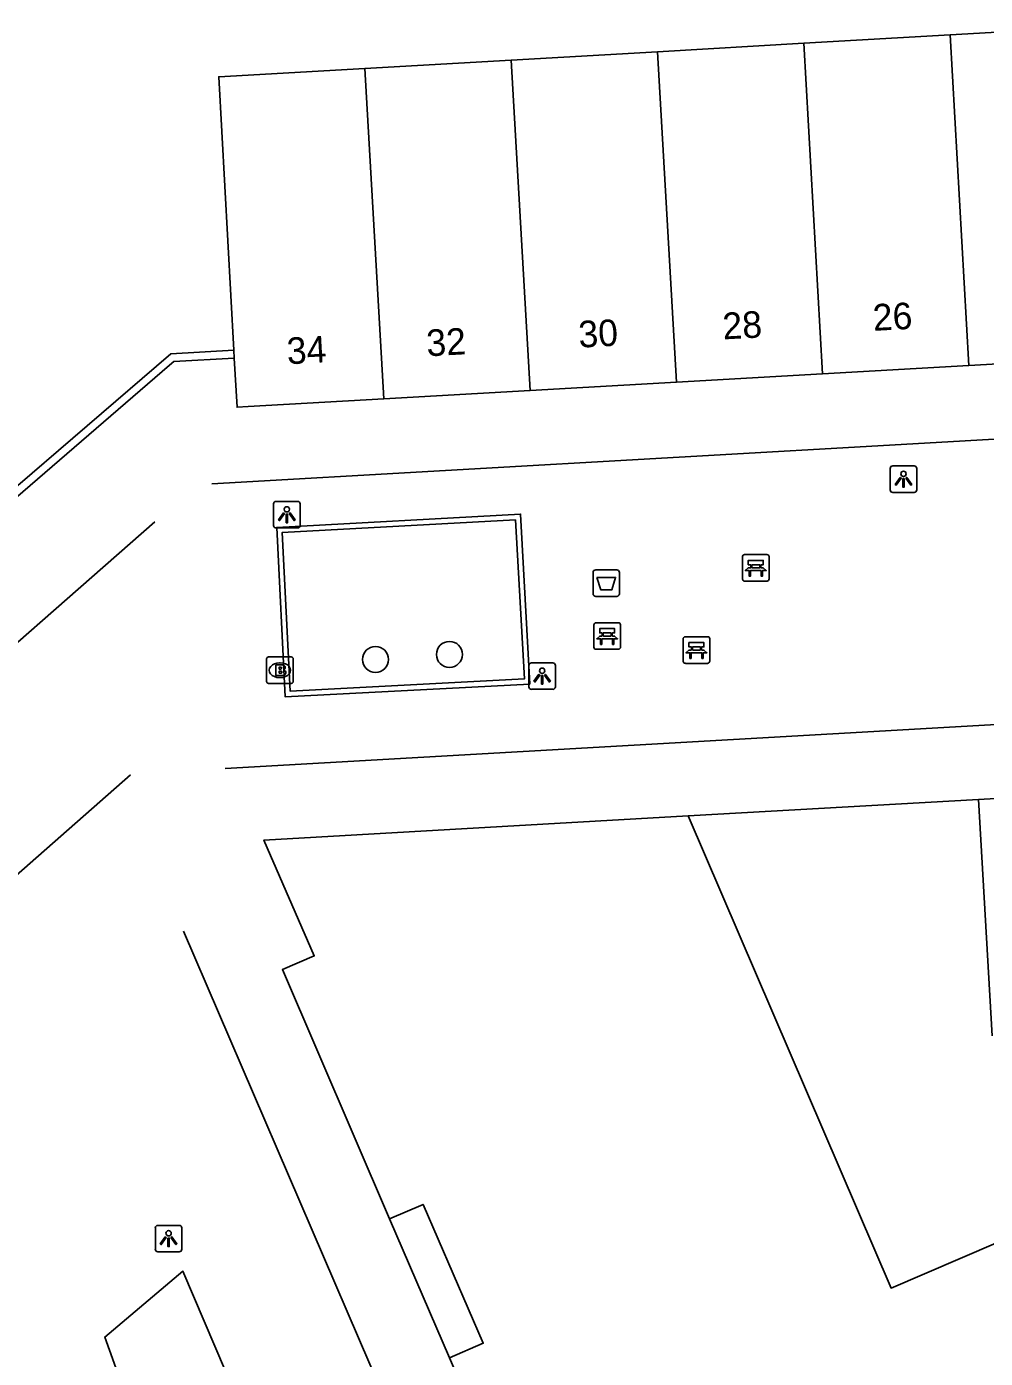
# Model space of a CAD drawing. Extents: x 155640 to 156810, y 382822 to 384046.
# Drawn here: x 156513.2 to 156549.2, y 383789.4 to 383839.5 of the extents above; entities that cross this region are included whole.
import ezdxf

# ---------------------------------------------------------------- set-up
doc = ezdxf.new("R2010")
doc.units = 0
for name, color, linetype in [('IMGEO_Afvalbak', 7, 'Continuous'), ('IMGEO_Bank', 7, 'Continuous'), ('IMGEO_Boom', 7, 'Continuous'), ('IMGEO_Brandkraan', 7, 'Continuous'), ('IMGEO_Lichtpunt', 7, 'Continuous'), ('IMGEO_Lijnafwatering', 7, 'Continuous'), ('IMGEO_Muur', 7, 'Continuous'), ('IMGEO_Pand', 7, 'Continuous'), ('IMGEO_Pand_nummerreeks', 7, 'Continuous'), ('IMGEO_Pand_overbouw', 7, 'Continuous'), ('IMGEO_Voetgangersgebied_open', 7, 'Continuous'), ('IMGEO_Voetpad_open', 7, 'Continuous')]:
    doc.layers.add(name, color=color, linetype=linetype)

msp = doc.modelspace()

# ---------------------------------------------------------------- linework, layer by layer
at = {"layer": 'IMGEO_Afvalbak'}
for p, q in [((156534.493, 383818.161), (156534.493, 383818.961)), ((156534.493, 383818.961), (156534.493, 383818.161)), ((156534.593, 383819.061), (156535.383, 383819.061)), ((156535.383, 383819.061), (156534.593, 383819.061)), ((156535.483, 383818.961), (156535.483, 383818.161)), ((156535.483, 383818.161), (156535.483, 383818.961)), ((156535.383, 383818.061), (156534.593, 383818.061)), ((156534.593, 383818.061), (156535.383, 383818.061))]:
    msp.add_line(p, q, dxfattribs=at)
msp.add_lwpolyline([(156534.636, 383818.775), (156535.34, 383818.775), (156535.191, 383818.305), (156534.785, 383818.305), (156534.636, 383818.775)], dxfattribs=at)
for centre, start, end in [((156534.593, 383818.961), 90, 180), ((156534.593, 383818.961), 90, 180), ((156535.383, 383818.961), 0, 90), ((156535.383, 383818.961), 360, 90), ((156534.593, 383818.161), 180, 270), ((156534.593, 383818.161), 180, 270), ((156535.383, 383818.161), 270, 0), ((156535.383, 383818.161), 270, 0)]:
    msp.add_arc(centre, 0.1, start, end, dxfattribs=at)
at = {"layer": 'IMGEO_Bank'}
for p, q in [((156540.11, 383818.709), (156540.11, 383819.55)), ((156540.11, 383819.55), (156540.11, 383818.709)), ((156540.185, 383819.634), (156541.026, 383819.634)), ((156541.026, 383819.634), (156540.185, 383819.634)), ((156541.11, 383819.559), (156541.11, 383818.718)), ((156541.11, 383818.718), (156541.11, 383819.559)), ((156540.807, 383819.032), (156540.414, 383819.032)), ((156540.419, 383819.14), (156540.419, 383819.246)), ((156540.463, 383819.246), (156540.463, 383819.14)), ((156540.751, 383819.252), (156540.469, 383819.252)), ((156540.469, 383819.134), (156540.751, 383819.134)), ((156540.757, 383819.14), (156540.757, 383819.246)), ((156540.801, 383819.246), (156540.801, 383819.14)), ((156541.035, 383818.634), (156540.194, 383818.634)), ((156540.194, 383818.634), (156541.035, 383818.634)), ((156534.523, 383816.146), (156534.523, 383816.987)), ((156534.523, 383816.987), (156534.523, 383816.146)), ((156534.598, 383817.071), (156535.439, 383817.071)), ((156535.439, 383817.071), (156534.598, 383817.071)), ((156535.523, 383816.996), (156535.523, 383816.155)), ((156535.523, 383816.155), (156535.523, 383816.996)), ((156535.22, 383816.469), (156534.827, 383816.469)), ((156534.832, 383816.577), (156534.832, 383816.683)), ((156534.876, 383816.683), (156534.876, 383816.577)), ((156535.164, 383816.689), (156534.882, 383816.689)), ((156534.882, 383816.571), (156535.164, 383816.571)), ((156535.17, 383816.577), (156535.17, 383816.683)), ((156535.214, 383816.683), (156535.214, 383816.577)), ((156537.88, 383815.618), (156537.88, 383816.459)), ((156537.88, 383816.459), (156537.88, 383815.618)), ((156537.955, 383816.543), (156538.796, 383816.543)), ((156538.796, 383816.543), (156537.955, 383816.543)), ((156538.88, 383816.468), (156538.88, 383815.627)), ((156538.88, 383815.627), (156538.88, 383816.468)), ((156535.448, 383816.071), (156534.607, 383816.071)), ((156534.607, 383816.071), (156535.448, 383816.071)), ((156538.577, 383815.941), (156538.184, 383815.941)), ((156538.189, 383816.049), (156538.189, 383816.155)), ((156538.233, 383816.155), (156538.233, 383816.049)), ((156538.521, 383816.161), (156538.239, 383816.161)), ((156538.239, 383816.043), (156538.521, 383816.043)), ((156538.527, 383816.049), (156538.527, 383816.155)), ((156538.571, 383816.155), (156538.571, 383816.049)), ((156538.805, 383815.543), (156537.964, 383815.543)), ((156537.964, 383815.543), (156538.805, 383815.543))]:
    msp.add_line(p, q, dxfattribs=at)
for points in [[(156540.413, 383819.252), (156540.327, 383819.252), (156540.327, 383819.413), (156540.89, 383819.413), (156540.89, 383819.252), (156540.807, 383819.252)], [(156540.357, 383819.032), (156540.215, 383819.032), (156540.327, 383819.134), (156540.413, 383819.134)], [(156540.407, 383819.025), (156540.407, 383818.818), (156540.364, 383818.818), (156540.364, 383819.025)], [(156540.807, 383819.134), (156540.89, 383819.134), (156541.002, 383819.032), (156540.863, 383819.032)], [(156540.857, 383819.025), (156540.857, 383818.818), (156540.813, 383818.818), (156540.813, 383819.025)], [(156534.826, 383816.689), (156534.74, 383816.689), (156534.74, 383816.85), (156535.303, 383816.85), (156535.303, 383816.689), (156535.22, 383816.689)], [(156534.77, 383816.469), (156534.628, 383816.469), (156534.74, 383816.571), (156534.826, 383816.571)], [(156534.82, 383816.462), (156534.82, 383816.255), (156534.777, 383816.255), (156534.777, 383816.462)], [(156535.22, 383816.571), (156535.303, 383816.571), (156535.415, 383816.469), (156535.276, 383816.469)], [(156535.27, 383816.462), (156535.27, 383816.255), (156535.226, 383816.255), (156535.226, 383816.462)], [(156538.183, 383816.161), (156538.097, 383816.161), (156538.097, 383816.322), (156538.66, 383816.322), (156538.66, 383816.161), (156538.577, 383816.161)], [(156538.127, 383815.941), (156537.985, 383815.941), (156538.097, 383816.043), (156538.183, 383816.043)], [(156538.177, 383815.934), (156538.177, 383815.727), (156538.134, 383815.727), (156538.134, 383815.934)], [(156538.577, 383816.043), (156538.66, 383816.043), (156538.772, 383815.941), (156538.633, 383815.941)], [(156538.627, 383815.934), (156538.627, 383815.727), (156538.583, 383815.727), (156538.583, 383815.934)]]:
    msp.add_lwpolyline(points, dxfattribs=at)
for centre, radius, start, end in [((156540.188, 383819.556), 0.0779, 92.4484, 184.2845), ((156540.188, 383819.556), 0.0779, 92.4484, 184.2845), ((156541.032, 383819.556), 0.0779, 2.4484, 94.2845), ((156541.032, 383819.556), 0.0779, 2.4484, 94.2845), ((156540.357, 383819.025), 0.00671, 2.8957, 87.1043), ((156540.414, 383819.025), 0.00671, 92.8957, 177.1043), ((156540.412, 383819.245), 0.00671, 2.8957, 87.1043), ((156540.412, 383819.141), 0.00671, 272.8957, 357.1043), ((156540.469, 383819.245), 0.00671, 92.8957, 177.1043), ((156540.469, 383819.141), 0.00671, 182.8957, 267.1043), ((156540.751, 383819.245), 0.00671, 2.8957, 87.1043), ((156540.751, 383819.141), 0.00671, 272.8957, 357.1043), ((156540.808, 383819.245), 0.00671, 92.8957, 177.1043), ((156540.808, 383819.141), 0.00671, 182.8957, 267.1043), ((156540.806, 383819.025), 0.00671, 2.8957, 87.1043), ((156540.863, 383819.025), 0.00671, 92.8957, 177.1043), ((156540.188, 383818.712), 0.0779, 182.4484, 274.2845), ((156540.188, 383818.712), 0.0779, 182.4484, 274.2845), ((156541.032, 383818.712), 0.0779, 272.4484, 4.2845), ((156541.032, 383818.712), 0.0779, 272.4484, 4.2845), ((156534.601, 383816.993), 0.0779, 92.4484, 184.2845), ((156534.601, 383816.993), 0.0779, 92.4484, 184.2845), ((156535.445, 383816.993), 0.0779, 2.4484, 94.2845), ((156535.445, 383816.993), 0.0779, 2.4484, 94.2845), ((156534.77, 383816.462), 0.00671, 2.8957, 87.1043), ((156534.827, 383816.462), 0.00671, 92.8957, 177.1043), ((156534.825, 383816.682), 0.00671, 2.8957, 87.1043), ((156534.825, 383816.578), 0.00671, 272.8957, 357.1043), ((156534.882, 383816.682), 0.00671, 92.8957, 177.1043), ((156534.882, 383816.578), 0.00671, 182.8957, 267.1043), ((156535.164, 383816.682), 0.00671, 2.8957, 87.1043), ((156535.164, 383816.578), 0.00671, 272.8957, 357.1043), ((156535.221, 383816.682), 0.00671, 92.8957, 177.1043), ((156535.221, 383816.578), 0.00671, 182.8957, 267.1043), ((156535.219, 383816.462), 0.00671, 2.8957, 87.1043), ((156535.276, 383816.462), 0.00671, 92.8957, 177.1043), ((156537.958, 383816.465), 0.0779, 92.4484, 184.2845), ((156537.958, 383816.465), 0.0779, 92.4484, 184.2845), ((156538.802, 383816.465), 0.0779, 2.4484, 94.2845), ((156538.802, 383816.465), 0.0779, 2.4484, 94.2845), ((156534.601, 383816.149), 0.0779, 182.4484, 274.2845), ((156534.601, 383816.149), 0.0779, 182.4484, 274.2845), ((156535.445, 383816.149), 0.0779, 272.4484, 4.2845), ((156535.445, 383816.149), 0.0779, 272.4484, 4.2845), ((156538.127, 383815.934), 0.00671, 2.8957, 87.1043), ((156538.184, 383815.934), 0.00671, 92.8957, 177.1043), ((156538.182, 383816.154), 0.00671, 2.8957, 87.1043), ((156538.182, 383816.05), 0.00671, 272.8957, 357.1043), ((156538.239, 383816.154), 0.00671, 92.8957, 177.1043), ((156538.239, 383816.05), 0.00671, 182.8957, 267.1043), ((156538.521, 383816.154), 0.00671, 2.8957, 87.1043), ((156538.521, 383816.05), 0.00671, 272.8957, 357.1043), ((156538.578, 383816.154), 0.00671, 92.8957, 177.1043), ((156538.578, 383816.05), 0.00671, 182.8957, 267.1043), ((156538.576, 383815.934), 0.00671, 2.8957, 87.1043), ((156538.633, 383815.934), 0.00671, 92.8957, 177.1043), ((156537.958, 383815.621), 0.0779, 182.4484, 274.2845), ((156537.958, 383815.621), 0.0779, 182.4484, 274.2845), ((156538.802, 383815.621), 0.0779, 272.4484, 4.2845), ((156538.802, 383815.621), 0.0779, 272.4484, 4.2845)]:
    msp.add_arc(centre, radius, start, end, dxfattribs=at)
at = {"layer": 'IMGEO_Boom'}
for centre in [(156529.09, 383815.878), (156526.311, 383815.689)]:
    msp.add_circle(centre, 0.489, dxfattribs=at)
at = {"layer": 'IMGEO_Brandkraan'}
for p, q in [((156522.216, 383814.859), (156522.216, 383815.711)), ((156522.291, 383815.785), (156523.143, 383815.785)), ((156522.704, 383815.565), (156522.729, 383815.565)), ((156523.217, 383815.711), (156523.217, 383814.859)), ((156522.727, 383815.005), (156522.702, 383815.005)), ((156523.143, 383814.785), (156522.291, 383814.785))]:
    msp.add_line(p, q, dxfattribs=at)
for points in [[(156522.216, 383814.859), (156522.216, 383815.711)], [(156522.291, 383815.785), (156523.143, 383815.785)], [(156522.564, 383815.485), (156522.564, 383815.085), (156522.777, 383815.085)], [(156522.795, 383815.485), (156522.564, 383815.485)], [(156522.743, 383815.404), (156522.689, 383815.404), (156522.689, 383815.328)], [(156522.689, 383815.328), (156522.742, 383815.328)], [(156523.217, 383815.711), (156523.217, 383814.859)], [(156522.751, 383815.252), (156522.689, 383815.252), (156522.689, 383815.171)], [(156522.689, 383815.171), (156522.751, 383815.171)], [(156523.143, 383814.785), (156522.291, 383814.785)]]:
    msp.add_lwpolyline(points, dxfattribs=at)
for centre, radius, start, end in [((156522.293, 383815.709), 0.0765, 91.552, 178.448), ((156522.293, 383815.709), 0.0765, 91.552, 178.448), ((156522.744, 383815.366), 0.0379, 267.8285, 90.9355), ((156522.799, 383815.34), 0.145, 59.4692, 91.5367), ((156522.824, 383815.387), 0.0922, 285.5137, 58.1501), ((156522.829, 383815.195), 0.105, 301.3115, 78.989), ((156523.141, 383815.709), 0.0765, 1.552, 88.448), ((156523.141, 383815.709), 0.0765, 1.552, 88.448), ((156522.293, 383814.861), 0.0765, 181.552, 268.448), ((156522.293, 383814.861), 0.0765, 181.552, 268.448), ((156522.752, 383815.211), 0.0404, 269.8759, 90.5077), ((156522.783, 383815.336), 0.251, 268.6676, 293.5347), ((156523.141, 383814.861), 0.0765, 271.552, 358.448), ((156523.141, 383814.861), 0.0765, 271.552, 358.448)]:
    msp.add_arc(centre, radius, start, end, dxfattribs=at)
for centre, major_axis, ratio, start_param, end_param in [((156522.703, 383815.285), (-0.387, 0.002), 0.722429, 4.712389, 7.853982), ((156522.728, 383815.285), (-0.39, 0.002), 0.717154, 1.570796, 4.712389)]:
    msp.add_ellipse(centre, major_axis=major_axis, ratio=ratio, start_param=start_param, end_param=end_param, dxfattribs=at)
at = {"layer": 'IMGEO_Lichtpunt'}
for p, q in [((156545.665, 383822.876), (156545.665, 383822.069)), ((156545.665, 383822.876), (156545.665, 383822.069)), ((156546.567, 383822.971), (156545.759, 383822.971)), ((156546.567, 383822.971), (156545.759, 383822.971)), ((156546.661, 383822.069), (156546.661, 383822.876)), ((156546.661, 383822.069), (156546.661, 383822.876)), ((156545.759, 383821.975), (156546.567, 383821.975)), ((156545.759, 383821.975), (156546.567, 383821.975)), ((156522.478, 383821.54), (156522.478, 383820.733)), ((156522.478, 383821.54), (156522.478, 383820.733)), ((156523.38, 383821.635), (156522.572, 383821.635)), ((156523.38, 383821.635), (156522.572, 383821.635)), ((156523.474, 383820.733), (156523.474, 383821.54)), ((156523.474, 383820.733), (156523.474, 383821.54)), ((156522.572, 383820.639), (156523.38, 383820.639)), ((156522.572, 383820.639), (156523.38, 383820.639)), ((156532.077, 383815.466), (156532.077, 383814.659)), ((156532.077, 383815.466), (156532.077, 383814.659)), ((156532.979, 383815.561), (156532.171, 383815.561)), ((156532.979, 383815.561), (156532.171, 383815.561)), ((156533.073, 383814.659), (156533.073, 383815.466)), ((156533.073, 383814.659), (156533.073, 383815.466)), ((156532.171, 383814.565), (156532.979, 383814.565)), ((156532.171, 383814.565), (156532.979, 383814.565)), ((156518.031, 383794.302), (156518.031, 383793.495)), ((156518.031, 383794.302), (156518.031, 383793.495)), ((156518.933, 383794.397), (156518.125, 383794.397)), ((156518.933, 383794.397), (156518.125, 383794.397)), ((156519.027, 383793.495), (156519.027, 383794.302)), ((156519.027, 383793.495), (156519.027, 383794.302)), ((156518.125, 383793.401), (156518.933, 383793.401)), ((156518.125, 383793.401), (156518.933, 383793.401))]:
    msp.add_line(p, q, dxfattribs=at)
for points in [[(156546.039, 383822.54), (156546.078, 383822.512), (156545.89, 383822.25), (156545.852, 383822.277), (156546.039, 383822.54)], [(156546.141, 383822.492), (156546.188, 383822.492), (156546.188, 383822.17), (156546.141, 383822.17), (156546.141, 383822.492)], [(156546.251, 383822.512), (156546.289, 383822.539), (156546.476, 383822.277), (156546.437, 383822.249), (156546.251, 383822.512)], [(156522.852, 383821.204), (156522.891, 383821.176), (156522.703, 383820.914), (156522.665, 383820.941), (156522.852, 383821.204)], [(156522.954, 383821.156), (156523.001, 383821.156), (156523.001, 383820.834), (156522.954, 383820.834), (156522.954, 383821.156)], [(156523.064, 383821.176), (156523.102, 383821.203), (156523.289, 383820.941), (156523.25, 383820.913), (156523.064, 383821.176)], [(156532.451, 383815.13), (156532.49, 383815.102), (156532.302, 383814.84), (156532.264, 383814.867), (156532.451, 383815.13)], [(156532.553, 383815.082), (156532.6, 383815.082), (156532.6, 383814.76), (156532.553, 383814.76), (156532.553, 383815.082)], [(156532.663, 383815.102), (156532.701, 383815.129), (156532.888, 383814.867), (156532.849, 383814.839), (156532.663, 383815.102)], [(156518.405, 383793.966), (156518.444, 383793.938), (156518.256, 383793.676), (156518.218, 383793.703), (156518.405, 383793.966)], [(156518.507, 383793.918), (156518.554, 383793.918), (156518.554, 383793.596), (156518.507, 383793.596), (156518.507, 383793.918)], [(156518.617, 383793.938), (156518.655, 383793.965), (156518.842, 383793.703), (156518.803, 383793.675), (156518.617, 383793.938)]]:
    msp.add_lwpolyline(points, dxfattribs=at)
for centre in [(156546.164, 383822.674), (156522.977, 383821.338), (156532.576, 383815.264), (156518.53, 383794.1)]:
    msp.add_circle(centre, 0.0994, dxfattribs=at)
for centre, start, end in [((156545.759, 383822.876), 90, 180), ((156545.759, 383822.876), 90, 180), ((156546.567, 383822.876), 0, 90), ((156546.567, 383822.876), 0, 90), ((156545.759, 383822.069), 180, 270), ((156545.759, 383822.069), 180, 270), ((156546.567, 383822.069), 270, 0), ((156546.567, 383822.069), 270, 360), ((156522.572, 383821.54), 90, 180), ((156522.572, 383821.54), 90, 180), ((156523.38, 383821.54), 0, 90), ((156523.38, 383821.54), 0, 90), ((156522.572, 383820.733), 180, 270), ((156522.572, 383820.733), 180, 270), ((156523.38, 383820.733), 270, 0), ((156523.38, 383820.733), 270, 360), ((156532.171, 383815.466), 90, 180), ((156532.171, 383815.466), 90, 180), ((156532.979, 383815.466), 0, 90), ((156532.979, 383815.466), 0, 90), ((156532.171, 383814.659), 180, 270), ((156532.171, 383814.659), 180, 270), ((156532.979, 383814.659), 270, 0), ((156532.979, 383814.659), 270, 360), ((156518.125, 383794.302), 90, 180), ((156518.125, 383794.302), 90, 180), ((156518.933, 383794.302), 0, 90), ((156518.933, 383794.302), 0, 90), ((156518.125, 383793.495), 180, 270), ((156518.125, 383793.495), 180, 270), ((156518.933, 383793.495), 270, 0), ((156518.933, 383793.495), 270, 360)]:
    msp.add_arc(centre, 0.0946, start, end, dxfattribs=at)
at = {"layer": 'IMGEO_Lijnafwatering'}
for points in [[(156572.094, 383825.268), (156546.51, 383823.806)], [(156546.51, 383823.806), (156520.157, 383822.301)], [(156518.012, 383820.864), (156509.034, 383812.994)], [(156573.301, 383814.59), (156547.243, 383813.106)], [(156547.243, 383813.106), (156520.651, 383811.592)], [(156517.098, 383811.348), (156504.298, 383800.086)], [(156526.985, 383787.107), (156519.088, 383805.472)]]:
    msp.add_lwpolyline(points, dxfattribs=at)
at = {"layer": 'IMGEO_Muur'}
for points in [[(156520.985, 383827.32), (156518.61, 383827.189), (156512.326, 383821.768), (156509.966, 383819.732), (156509.801, 383819.59), (156510.006, 383819.379)], [(156510.006, 383819.379), (156518.564, 383826.758), (156518.723, 383826.895), (156521.001, 383827.021)], [(156532.119, 383814.765), (156522.912, 383814.285), (156522.596, 383820.66), (156531.766, 383821.156), (156532.119, 383814.765)], [(156531.578, 383820.945), (156522.806, 383820.471), (156523.102, 383814.495), (156531.908, 383814.955), (156531.578, 383820.945)], [(156548.99, 383810.421), (156538.063, 383809.8)]]:
    msp.add_lwpolyline(points, dxfattribs=at)
at = {"layer": 'IMGEO_Pand'}
for points in [[(156547.914, 383839.185), (156553.414, 383839.499)], [(156536.915, 383838.556), (156542.414, 383838.871)], [(156542.414, 383838.871), (156547.914, 383839.185)], [(156543.125, 383826.437), (156542.414, 383838.871)], [(156547.914, 383839.185), (156548.624, 383826.751)], [(156531.415, 383838.242), (156536.915, 383838.556)], [(156537.625, 383826.123), (156536.915, 383838.556)], [(156525.915, 383837.928), (156520.415, 383837.614), (156520.985, 383827.32)], [(156525.915, 383837.928), (156531.415, 383838.242)], [(156526.625, 383825.495), (156525.915, 383837.928)], [(156532.125, 383825.809), (156531.415, 383838.242)], [(156521.001, 383827.021), (156520.985, 383827.32)], [(156521.001, 383827.021), (156521.103, 383825.18), (156521.521, 383825.204), (156526.625, 383825.495)], [(156554.124, 383827.065), (156548.624, 383826.751)], [(156543.125, 383826.437), (156537.625, 383826.123)], [(156548.624, 383826.751), (156543.125, 383826.437)], [(156537.625, 383826.123), (156532.125, 383825.809)], [(156532.125, 383825.809), (156526.625, 383825.495)], [(156619.306, 383814.422), (156620.197, 383799.996), (156597.327, 383798.583), (156599.334, 383793.861), (156599.125, 383793.772), (156601.176, 383788.945), (156600.332, 383788.586), (156594.507, 383802.295), (156565.638, 383800.613), (156545.7, 383792.039), (156538.063, 383809.8)], [(156548.99, 383810.421), (156554.66, 383810.744)], [(156548.99, 383810.421), (156549.495, 383801.524)], [(156526.841, 383794.638), (156522.809, 383804.019), (156524.005, 383804.534), (156522.114, 383808.892), (156538.063, 383809.8)], [(156526.841, 383794.638), (156528.101, 383795.184), (156530.363, 383789.96), (156529.087, 383789.41)], [(156538.691, 383767.078), (156529.087, 383789.41)]]:
    msp.add_lwpolyline(points, dxfattribs=at)
at = {"layer": 'IMGEO_Pand_overbouw'}
msp.add_lwpolyline([(156529.087, 383789.41), (156530.363, 383789.96), (156528.101, 383795.184), (156526.841, 383794.638)], close=True, dxfattribs=at)
at = {"layer": 'IMGEO_Voetgangersgebied_open'}
for points in [[(156529.087, 383789.41), (156526.841, 383794.638)], [(156519.85, 383776.428), (156515.42, 383781.667), (156517.905, 383785.259), (156516.126, 383790.192), (156519.07, 383792.672), (156525.122, 383778.477), (156519.85, 383776.428)]]:
    msp.add_lwpolyline(points, dxfattribs=at)
at = {"layer": 'IMGEO_Voetpad_open'}
msp.add_lwpolyline([(156538.063, 383809.8), (156548.99, 383810.421)], dxfattribs=at)

# ---------------------------------------------------------------- texts
at = {"layer": 'IMGEO_Pand_nummerreeks'}
for s, rotation, p in [('26', 3.0711, (156545.035, 383828.051)), ('30', 3.0711, (156533.967, 383827.419)), ('28', 3.0711, (156539.383, 383827.729)), ('34', 3.0997, (156523, 383826.793)), ('32', 3.0711, (156528.249, 383827.093))]:
    msp.add_text(s, height=1, rotation=rotation, dxfattribs=at).set_placement(p)

doc.saveas('drawing.dxf')
